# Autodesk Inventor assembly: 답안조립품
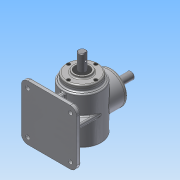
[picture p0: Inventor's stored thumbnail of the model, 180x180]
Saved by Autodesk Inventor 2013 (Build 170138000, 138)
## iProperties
Created: 2015-07
Part Number: 답안조립품
Document SubType Name: Assembly
Designer: Administrator
Author: Administrator
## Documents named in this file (14)
- C:\Users\Administrator\Desktop\450706V1011\답안조립품.iam
- C:\Users\Administrator\Desktop\450706V1011\본체.ipt
- C:\Users\Administrator\Desktop\450706V1011\커버.ipt
- C:\Users\Administrator\Desktop\450706V1011\M4.ipt
- C:\Users\Administrator\Desktop\450706V1011\오일실.ipt
- C:\Users\Administrator\Desktop\450706V1011\베어링 6203.ipt
- C:\Users\Administrator\Desktop\450706V1011\메인 축.ipt
- 메인 축.ipt
- C:\Users\Administrator\Desktop\450706V1011\키 5x5.ipt
- C:\Users\Administrator\Desktop\450706V1011\서브 축.ipt
- 서브 축.ipt
- C:\Users\Administrator\Desktop\450706V1011\키 4x4.ipt
- C:\Users\Administrator\Desktop\450706V1011\메인 베벨기어.ipt
- C:\Users\Administrator\Desktop\450706V1011\서브 베벨기어.ipt
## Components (8 placed, 1 different names)
1. M4:1
2. M4:3
3. M4:4
4. M4:5
5. M4:2
6. M4:6
7. M4:7
8. M4:8
